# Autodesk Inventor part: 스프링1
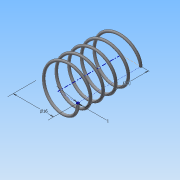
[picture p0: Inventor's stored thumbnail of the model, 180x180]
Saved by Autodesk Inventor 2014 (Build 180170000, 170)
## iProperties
Created: 2015-06
Part Number: 스프링1
Material: 강철, 연강
Document SubType Name: Modeling
Designer: Administrator
Density: 7.86 g/cm^3
Appearance: 강철
Mass: 1.52988 g
Surface Area: 7.87024 cm^2
Volume: 0.194641 cm^3
Author: Administrator
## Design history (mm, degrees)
sketch "스케치1"
  geometry: L1 (0, 0)-(8, 0); L2 (8, 0)-(8, 14.5); L3 (8, 14.5)-(0, 14.5); L4 (0, 14.5)-(0, 0); C1 r 0.5 at (8, 0)
  constraints: 8 end point, 2 parallel, 1 centre point, 1 coincident, 1 horizontal, 1 perpendicular
  dimensions: "d0" = 16 diameter of L2 L4; "d1" = 14.5 distance of L1.end L2.end (derived); "d2" = 1 diameter of C1
feature "코일1" sketch "스케치1" pitch "d3" = 10; turns "d5" = 5; dims "d4" = 14.5 (= d1), "d6" = 0, angle "d7" = 90 deg, angle "d8" = 90 deg, "d9" = 0, "d10" = 0
node "작업 평면1"
sketch "스케치2"
  geometry: L1 (-8.5, 0)-(-7.5, 0) reference; 1 further point
  constraints: 1 horizontal alignment
extrude "돌출1" cut sketch "스케치2" stored distance "d12" = 10; taper "d13" = 0 deg
node "작업 평면2"
sketch "스케치3"
  geometry: L1 (-7.5, 0)-(-8.5, 0) reference; 1 further point
  constraints: 1 horizontal alignment
extrude "돌출2" cut sketch "스케치3" stored distance "d15" = 10; taper "d16" = 0 deg
node "솔리드1"
node "절단 모서리 투영1"
node "절단 모서리 투영2"
other parameters: "d11" = 0, "d14" = 14.5 (= d1)
